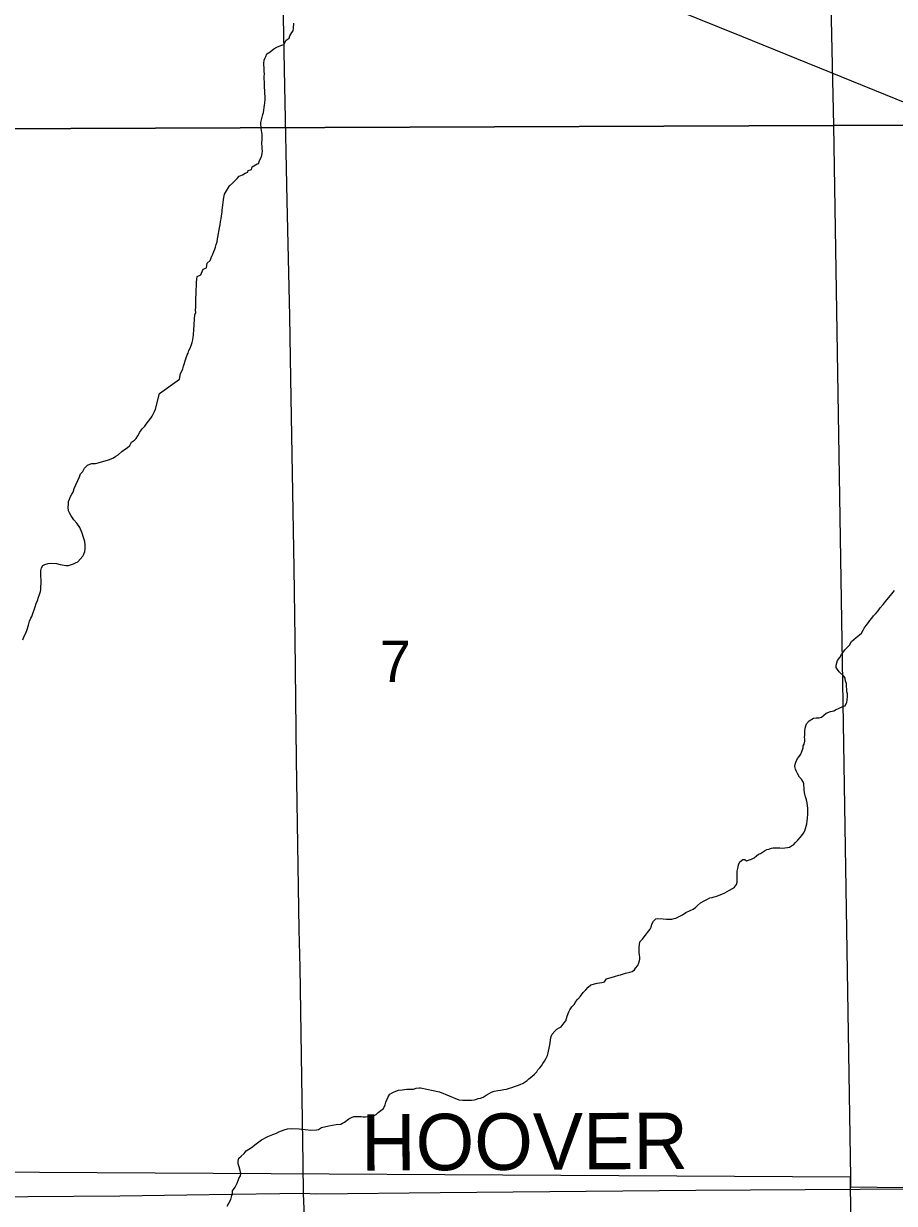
# Model space of a CAD drawing. Extents: x 10.6 to 44.6, y -2.6 to 23.4.
# Drawn here: x 18.308 to 19.186, y 16.595 to 17.784 of the extents above; entities that cross this region are included whole.
import ezdxf

# ---------------------------------------------------------------- set-up
doc = ezdxf.new("R2010")
doc.units = 0
for name, color, linetype in [('GM_X_County_Road', 7, 'Continuous'), ('GM_X_Minor_River', 7, 'Continuous'), ('GM_X_Section', 7, 'Continuous'), ('GM_X_Section_Text', 7, 'Continuous'), ('GM_X_Township_Road', 7, 'Continuous'), ('GM_X_Township_Road_Text', 7, 'Continuous'), ('GM_X_US_Route', 7, 'Continuous')]:
    doc.layers.add(name, color=color, linetype=linetype)

msp = doc.modelspace()

# ---------------------------------------------------------------- linework, layer by layer
at = {"layer": 'GM_X_County_Road'}
for points in [[(18.5905, 16.6049), (18.5903, 16.6355), (18.5888, 16.722), (18.5871, 16.8327), (18.5864, 16.8707), (18.5837, 17.0419), (18.5822, 17.1636), (18.5811, 17.2351), (18.578, 17.426), (18.577, 17.4889), (18.5741, 17.6053), (18.5717, 17.7206), (18.5702, 17.8073), (18.568, 17.9494), (18.5668, 17.9597)], [(18.6048, 15.5857), (18.6032, 15.5983), (18.6025, 15.6406), (18.6005, 15.8397), (18.5996, 15.9005), (18.5979, 16.0491), (18.5954, 16.2436), (18.5932, 16.4305), (18.5925, 16.4749), (18.5913, 16.5895), (18.5905, 16.6049)]]:
    msp.add_lwpolyline(points, dxfattribs=at)
at = {"layer": 'GM_X_Minor_River'}
for points in [[(18.5507, 17.6966), (18.551, 17.6992), (18.5517, 17.7034), (18.5519, 17.7076), (18.5519, 17.7107), (18.5518, 17.7129), (18.5518, 17.7148), (18.5518, 17.7167), (18.5513, 17.719), (18.5513, 17.7221), (18.5512, 17.7251), (18.5511, 17.7278), (18.5511, 17.73), (18.5514, 17.7335), (18.551, 17.7353), (18.5509, 17.7376), (18.5509, 17.7395), (18.5505, 17.7418), (18.5508, 17.7437), (18.5511, 17.7468), (18.5518, 17.7487), (18.5526, 17.7506), (18.5536, 17.7533), (18.557, 17.7552), (18.5608, 17.7584), (18.5638, 17.7599), (18.566, 17.7611), (18.5679, 17.7616), (18.5709, 17.7628), (18.5731, 17.767), (18.5761, 17.769), (18.5768, 17.7713), (18.5787, 17.7747), (18.5802, 17.7766), (18.5805, 17.7793), (18.5808, 17.7843)], [(18.4456, 17.411), (18.4655, 17.4253), (18.4665, 17.431), (18.4684, 17.4341), (18.4691, 17.436), (18.4698, 17.4387), (18.4705, 17.4406), (18.4712, 17.444), (18.4726, 17.4479), (18.4734, 17.4498), (18.4745, 17.4517), (18.4752, 17.4544), (18.4763, 17.4567), (18.4773, 17.4594), (18.4784, 17.4624), (18.4791, 17.4651), (18.4794, 17.4678), (18.4798, 17.4697), (18.48, 17.4758), (18.4803, 17.4796), (18.4803, 17.4819), (18.4806, 17.4845), (18.4809, 17.4864), (18.4812, 17.4902), (18.482, 17.4925), (18.4819, 17.4948), (18.4822, 17.4979), (18.4822, 17.5001), (18.4821, 17.5036), (18.4821, 17.5055), (18.482, 17.5077), (18.4823, 17.5108), (18.4823, 17.5131), (18.4826, 17.5165), (18.4829, 17.5184), (18.4829, 17.5211), (18.4828, 17.5233), (18.4835, 17.529), (18.4872, 17.5306), (18.4894, 17.5364), (18.4928, 17.5376), (18.4935, 17.5422), (18.4964, 17.5449), (18.4982, 17.5495), (18.4993, 17.5514), (18.5001, 17.5541), (18.5011, 17.5564), (18.5019, 17.5583), (18.5026, 17.561), (18.5037, 17.5637), (18.504, 17.5667), (18.5043, 17.5686), (18.505, 17.5721), (18.5053, 17.5744), (18.506, 17.5778), (18.5067, 17.5809), (18.507, 17.5843), (18.5077, 17.587), (18.508, 17.59), (18.5087, 17.5938), (18.5087, 17.5957), (18.509, 17.598), (18.5093, 17.6011), (18.5097, 17.603), (18.51, 17.6064), (18.511, 17.6117), (18.5121, 17.6137), (18.5161, 17.6202), (18.5191, 17.6229), (18.5236, 17.6276), (18.5258, 17.6299), (18.5292, 17.6315), (18.5318, 17.6331), (18.5345, 17.6339), (18.5348, 17.6358), (18.5382, 17.6366), (18.5389, 17.6393), (18.5438, 17.6425), (18.5457, 17.6429), (18.546, 17.6452), (18.5475, 17.6482), (18.5486, 17.6509), (18.5489, 17.6532), (18.5493, 17.6551), (18.5488, 17.6578), (18.5488, 17.6601), (18.5487, 17.6623), (18.5487, 17.6642), (18.549, 17.6661), (18.549, 17.6692), (18.5489, 17.6722), (18.5485, 17.6741), (18.5484, 17.676), (18.548, 17.6779), (18.548, 17.6798), (18.5476, 17.6817), (18.5475, 17.684), (18.5489, 17.6893), (18.5496, 17.692), (18.5503, 17.6943), (18.5507, 17.6966)], [(18.438, 17.3881), (18.4391, 17.3901), (18.4406, 17.3928), (18.4413, 17.3951), (18.4456, 17.411)], [(18.3077, 17.1626), (18.3091, 17.1664), (18.3106, 17.1695), (18.312, 17.1733), (18.3134, 17.1775), (18.3145, 17.1814), (18.3159, 17.1845), (18.3167, 17.1864), (18.3181, 17.1902), (18.3192, 17.1929), (18.3202, 17.196), (18.3213, 17.1994), (18.3224, 17.2025), (18.3235, 17.2056), (18.3245, 17.2086), (18.3256, 17.2113), (18.3259, 17.2136), (18.3259, 17.2163), (18.3262, 17.2197), (18.3261, 17.2235), (18.326, 17.2262), (18.3259, 17.2296), (18.3259, 17.2326), (18.3266, 17.2353), (18.328, 17.2376), (18.3299, 17.2388), (18.3333, 17.2396), (18.336, 17.2401), (18.3417, 17.2398), (18.3455, 17.2388), (18.3513, 17.2378), (18.3539, 17.2378), (18.3569, 17.2387), (18.3588, 17.2395), (18.3607, 17.2403), (18.363, 17.2415), (18.3682, 17.2469), (18.3693, 17.2492), (18.3703, 17.2519), (18.3707, 17.2546), (18.3706, 17.258), (18.3701, 17.2618), (18.3689, 17.2659), (18.3676, 17.2701), (18.3652, 17.2758), (18.3621, 17.2802), (18.359, 17.2836), (18.3566, 17.2877), (18.3546, 17.2907), (18.3538, 17.2926), (18.3533, 17.2964), (18.3536, 17.2995), (18.3536, 17.3021), (18.3547, 17.3044), (18.3558, 17.3071), (18.3572, 17.3094), (18.3583, 17.3117), (18.3594, 17.3152), (18.3612, 17.319), (18.363, 17.3233), (18.3648, 17.3271), (18.3659, 17.3302), (18.3681, 17.3325), (18.3699, 17.3356), (18.3729, 17.3387), (18.3771, 17.3403), (18.3809, 17.3404), (18.3835, 17.3412), (18.3941, 17.3441), (18.3968, 17.345), (18.399, 17.3462), (18.4013, 17.3477), (18.4039, 17.3493), (18.4076, 17.3524), (18.4102, 17.3544), (18.4129, 17.3564), (18.4155, 17.3587), (18.4173, 17.3618), (18.4203, 17.3638), (18.4221, 17.3657), (18.4236, 17.3684), (18.4258, 17.3719), (18.428, 17.3754), (18.4306, 17.3781), (18.4321, 17.38), (18.4343, 17.3831), (18.4369, 17.3862), (18.438, 17.3881)], [(19.0977, 17.078), (19.1003, 17.0811), (19.1048, 17.0838), (19.1075, 17.0843), (19.1105, 17.0843), (19.1128, 17.0848), (19.1176, 17.0887), (19.1218, 17.0907), (19.1252, 17.0911), (19.127, 17.0923), (19.1304, 17.0939), (19.1342, 17.0955), (19.1365, 17.0963), (19.1383, 17.0998), (19.1386, 17.1021), (19.1389, 17.1055), (19.1389, 17.1082), (19.1384, 17.1105), (19.1384, 17.1124), (19.1379, 17.1165), (19.1379, 17.1188), (19.137, 17.1211), (19.1366, 17.1241), (19.1354, 17.126), (19.1307, 17.1305), (19.1288, 17.1327), (19.1276, 17.135), (19.1275, 17.1373), (19.1283, 17.1396), (19.129, 17.1419), (19.1312, 17.1449), (19.133, 17.148), (19.1348, 17.1507), (19.1363, 17.1527), (19.1382, 17.1546), (19.1408, 17.1573), (19.143, 17.1612), (19.1478, 17.1651), (19.1512, 17.1679), (19.1531, 17.1694), (19.1549, 17.1725), (19.1556, 17.1744), (19.1578, 17.1771), (19.16, 17.1802), (19.1615, 17.1822), (19.1634, 17.1845), (19.1652, 17.1868), (19.1674, 17.1892), (19.1697, 17.1919), (19.1719, 17.195), (19.1748, 17.1985), (19.1785, 17.2031), (19.1822, 17.2074), (19.1863, 17.2124)], [(18.966, 16.8824), (18.9694, 16.884), (18.9728, 16.8856), (18.9761, 16.8879), (18.9803, 16.8899), (18.9833, 16.8915), (18.9859, 16.8931), (18.9878, 16.8951), (18.9908, 16.8978), (18.9945, 16.8998), (18.9979, 16.9014), (19.0002, 16.9026), (19.0024, 16.903), (19.0047, 16.9038), (19.0073, 16.9046), (19.0096, 16.9054), (19.0122, 16.9066), (19.0153, 16.9079), (19.0175, 16.9091), (19.0201, 16.9106), (19.0231, 16.9122), (19.025, 16.9134), (19.0272, 16.9161), (19.0276, 16.9184), (19.0279, 16.9207), (19.0278, 16.9237), (19.0277, 16.9272), (19.0277, 16.9295), (19.0287, 16.9337), (19.0291, 16.936), (19.0305, 16.939), (19.0335, 16.9414), (19.0354, 16.9414), (19.0373, 16.9399), (19.0422, 16.9416), (19.0449, 16.9432), (19.0471, 16.9451), (19.0494, 16.9467), (19.0512, 16.9475), (19.0554, 16.9502), (19.0576, 16.9514), (19.0595, 16.9519), (19.0622, 16.9527), (19.064, 16.9531), (19.0659, 16.9531), (19.069, 16.9532), (19.0709, 16.9533), (19.0739, 16.9529), (19.0758, 16.953), (19.0785, 16.9534), (19.0804, 16.9539), (19.0826, 16.955), (19.0845, 16.9562), (19.0864, 16.9586), (19.089, 16.9609), (19.0912, 16.9636), (19.093, 16.9656), (19.0945, 16.9679), (19.096, 16.9702), (19.0967, 16.9725), (19.0981, 16.9775), (19.0984, 16.9801), (19.0987, 16.9832), (19.099, 16.987), (19.0989, 16.9904), (19.0989, 16.9931), (19.0985, 16.9954), (19.0984, 16.9984), (19.0976, 17.0014), (19.0967, 17.0045), (19.0959, 17.0071), (19.0955, 17.009), (19.0954, 17.0113), (19.0954, 17.014), (19.0949, 17.0158), (19.0949, 17.0178), (19.0941, 17.0196), (19.0925, 17.0223), (19.0906, 17.0245), (19.089, 17.0275), (19.0874, 17.0301), (19.0866, 17.0324), (19.0858, 17.0351), (19.0861, 17.0374), (19.0868, 17.0396), (19.0886, 17.0431), (19.0901, 17.0451), (19.0919, 17.0474), (19.093, 17.0501), (19.0941, 17.0539), (19.0944, 17.0558), (19.0951, 17.0577), (19.0958, 17.0608), (19.0958, 17.0627), (19.0957, 17.0646), (19.0961, 17.0665), (19.096, 17.0688), (19.096, 17.0707), (19.0963, 17.0737), (19.097, 17.076), (19.0977, 17.078)], [(18.7277, 16.7072), (18.7473, 16.6993), (18.7511, 16.6987), (18.7545, 16.6987), (18.7564, 16.6988), (18.7599, 16.6989), (18.7625, 16.6993), (18.7644, 16.6997), (18.7667, 16.7005), (18.7689, 16.701), (18.7716, 16.7018), (18.7746, 16.7038), (18.7776, 16.7057), (18.7802, 16.7069), (18.7829, 16.7078), (18.7866, 16.7086), (18.7893, 16.709), (18.7927, 16.7095), (18.7954, 16.7099), (18.7984, 16.7108), (18.8007, 16.7116), (18.8033, 16.7128), (18.8063, 16.7136), (18.8089, 16.7148), (18.812, 16.716), (18.8142, 16.7172), (18.8161, 16.7188), (18.8179, 16.7203), (18.8209, 16.7227), (18.8235, 16.725), (18.8258, 16.7274), (18.8269, 16.7293), (18.8287, 16.7316), (18.8306, 16.7336), (18.832, 16.7359), (18.8335, 16.7382), (18.835, 16.7405), (18.8364, 16.744), (18.8371, 16.7467), (18.8385, 16.7528), (18.8392, 16.7566), (18.8395, 16.7596), (18.8402, 16.7631), (18.8413, 16.7654), (18.8439, 16.7685), (18.8461, 16.7705), (18.8483, 16.7716), (18.8502, 16.7728), (18.8532, 16.7767), (18.855, 16.7787), (18.8557, 16.7813), (18.8564, 16.7836), (18.8579, 16.7879), (18.859, 16.7898), (18.8612, 16.7929), (18.8638, 16.7956), (18.8649, 16.7979), (18.8671, 16.8006), (18.8697, 16.8037), (18.8726, 16.8072), (18.8752, 16.8099), (18.8775, 16.8127), (18.8801, 16.815), (18.8865, 16.8167), (18.8914, 16.8175), (18.8941, 16.818), (18.8959, 16.8211), (18.9042, 16.8235), (18.9084, 16.8248), (18.9103, 16.8252), (18.9152, 16.8268), (18.9197, 16.8277), (18.922, 16.8285), (18.9242, 16.8301), (18.9253, 16.832), (18.9275, 16.8347), (18.9286, 16.8374), (18.9297, 16.8408), (18.9296, 16.8431), (18.9292, 16.845), (18.9288, 16.8481), (18.9291, 16.8504), (18.929, 16.853), (18.9294, 16.8553), (18.9297, 16.8584), (18.9323, 16.8611), (18.9341, 16.8634), (18.9352, 16.8653), (18.9374, 16.8677), (18.94, 16.8712), (18.9411, 16.8731), (18.9418, 16.8761), (18.9433, 16.8792), (18.9459, 16.8816), (18.9478, 16.882), (18.9531, 16.8817), (18.9565, 16.8814), (18.96, 16.8811), (18.9619, 16.8812), (18.9641, 16.882), (18.966, 16.8824)], [(18.6391, 16.6815), (18.6413, 16.6823), (18.6448, 16.6824), (18.6486, 16.6825), (18.6508, 16.6822), (18.6531, 16.6822), (18.6554, 16.6823), (18.6577, 16.6823), (18.66, 16.6824), (18.6637, 16.6843), (18.666, 16.6863), (18.6686, 16.6886), (18.6712, 16.6906), (18.673, 16.6941), (18.6737, 16.6967), (18.6748, 16.6998), (18.6759, 16.7021), (18.6777, 16.7048), (18.68, 16.7064), (18.6819, 16.7072), (18.6864, 16.7088), (18.6902, 16.7093), (18.6947, 16.7098), (18.6989, 16.7099), (18.7016, 16.7099), (18.7042, 16.7108), (18.7073, 16.7112), (18.7084, 16.7112), (18.7277, 16.7072)], [(18.5136, 16.5919), (18.5155, 16.595), (18.5173, 16.5988), (18.5183, 16.6027), (18.519, 16.6053), (18.519, 16.6076), (18.5216, 16.6111), (18.5238, 16.6153), (18.5248, 16.618), (18.5256, 16.6199), (18.527, 16.6226), (18.5273, 16.6249), (18.5269, 16.628), (18.5257, 16.6317), (18.5248, 16.6348), (18.5248, 16.6374), (18.5255, 16.6405), (18.5277, 16.6424), (18.5307, 16.6452), (18.5329, 16.6479), (18.5382, 16.6511), (18.543, 16.655), (18.5483, 16.6589), (18.5547, 16.6621), (18.5596, 16.6641), (18.5633, 16.6657), (18.5656, 16.6669), (18.5686, 16.6681), (18.5712, 16.6689), (18.5746, 16.6701), (18.5788, 16.6702), (18.5864, 16.67), (18.5922, 16.6694), (18.5979, 16.6688), (18.6036, 16.6689), (18.6059, 16.6693), (18.6089, 16.6713), (18.616, 16.673), (18.6236, 16.6743), (18.6282, 16.6748), (18.6301, 16.6756), (18.6319, 16.6768), (18.6364, 16.6799), (18.6391, 16.6815)]]:
    msp.add_lwpolyline(points, dxfattribs=at)
at = {"layer": 'GM_X_Section'}
for points in [[(20.0033, 18.797), (19.1006, 18.7791), (19.125, 17.681), (20.0033, 17.685)], [(20.0033, 17.685), (19.125, 17.681), (19.1418, 16.6213), (19.1419, 16.6144), (19.1419, 16.6116), (20.0033, 16.6008)], [(19.1603, 15.5267), (19.1419, 16.6116), (19.1419, 16.6144), (19.1418, 16.6213), (18.2074, 16.6265), (18.2299, 15.5267)]]:
    msp.add_lwpolyline(points, dxfattribs=at)
for points in [[(18.1656, 18.7612), (19.1006, 18.7791), (19.125, 17.681), (18.1848, 17.6775)], [(18.1848, 17.6775), (19.125, 17.681), (19.1418, 16.6213), (18.2074, 16.6265)]]:
    msp.add_lwpolyline(points, close=True, dxfattribs=at)
at = {"layer": 'GM_X_Township_Road'}
msp.add_lwpolyline([(19.5991, 16.6126), (19.5366, 16.6119), (19.2619, 16.6095), (18.9861, 16.6077), (18.7284, 16.6054), (18.6038, 16.6042), (18.5905, 16.6049), (18.4954, 16.6035), (18.4056, 16.6021), (18.3128, 16.6014), (18.2258, 16.6007), (18.107, 16.5993), (18.0035, 16.5982), (17.9186, 16.5972), (17.821, 16.5964), (17.788, 16.5964)], dxfattribs=at)
at = {"layer": 'GM_X_US_Route'}
msp.add_lwpolyline([(18.6315, 17.9333), (18.762, 17.8801), (19.0322, 17.771), (19.2878, 17.6674), (19.4378, 17.6063), (19.483, 17.588)], dxfattribs=at)

# ---------------------------------------------------------------- texts
at = {"layer": 'GM_X_Section_Text'}
msp.add_text('7', height=0.0419, rotation=0, dxfattribs=at).set_placement((18.6676, 17.1201))
at = {"layer": 'GM_X_Township_Road_Text'}
msp.add_text('HOOVER', height=0.05682, rotation=0.3294, dxfattribs=at).set_placement((18.6489, 16.6278))

doc.saveas('drawing.dxf')
